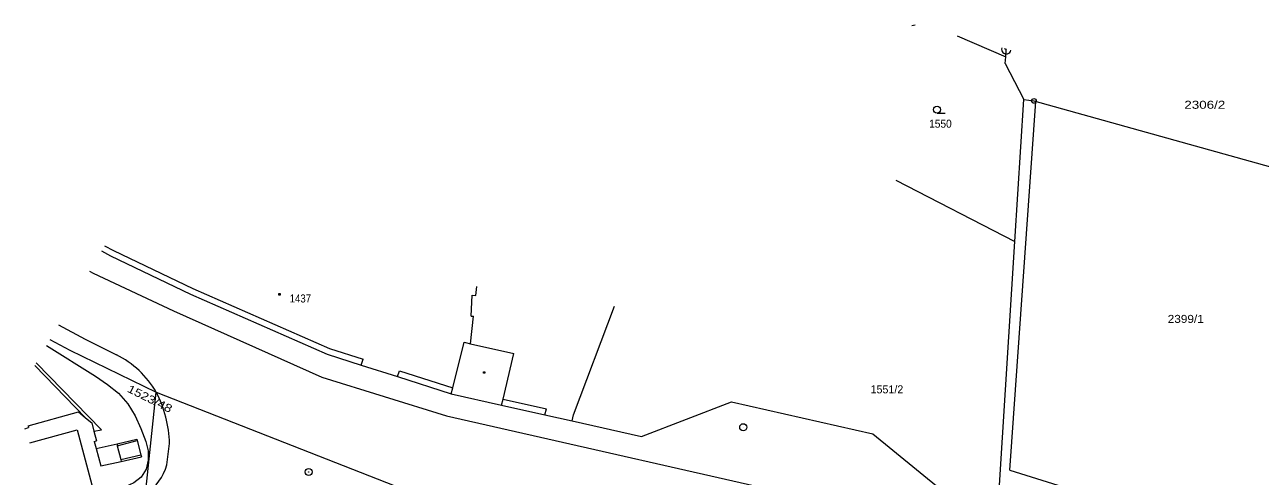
# Model space of a CAD drawing. Extents: x -630464 to -630140, y -1004543 to -1004208.
# Drawn here: x -630461.7 to -630330.5, y -1004256.3 to -1004208.4 of the extents above; entities that cross this region are included whole.
import ezdxf

# ---------------------------------------------------------------- set-up
doc = ezdxf.new("R2010")
doc.units = 0
doc.header["$LTSCALE"] = 0.34
for name, color, linetype, lineweight in [('1', 7, 'Continuous', 13), ('2', 7, 'Continuous', 13), ('23', 7, 'Continuous', 13), ('25', 7, 'Continuous', 13), ('28', 7, 'Continuous', 13)]:
    doc.layers.add(name, color=color, linetype=linetype, lineweight=lineweight)
doc.layers.add('14', color=7, linetype='Continuous')
doc.layers.add('15', color=7, linetype='Continuous')

msp = doc.modelspace()

# ---------------------------------------------------------------- linework, layer by layer
at = {"layer": '1'}
for p, q in [((-630367.482, -1004208.456), (-630367.141, -1004208.355)), ((-630357.678, -1004210.884), (-630357.45, -1004210.96)), ((-630357.45, -1004210.96), (-630357.449, -1004210.945)), ((-630357.56, -1004212.49), (-630355.58, -1004216.31)), ((-630356.54, -1004231.37), (-630355.58, -1004216.31)), ((-630369.197, -1004224.868), (-630356.54, -1004231.37)), ((-630358.18, -1004257.25), (-630356.54, -1004231.37)), ((-630453.543, -1004232.382), (-630452.58, -1004232.91)), ((-630403.43, -1004249.79), (-630399.057, -1004238.251)), ((-630459.017, -1004241.765), (-630456.91, -1004242.93)), ((-630456.91, -1004242.93), (-630447.73, -1004247.37)), ((-630448.86, -1004258.16), (-630447.73, -1004247.37)), ((-630447.73, -1004247.37), (-630421.48, -1004257.69)), ((-630403.57, -1004250.43), (-630403.43, -1004249.79)), ((-630403.57, -1004250.43), (-630396.18, -1004252.07))]:
    msp.add_line(p, q, dxfattribs=at)
for points in [[(-630357.56, -1004212.49), (-630357.51, -1004211.76), (-630357.45, -1004210.96)], [(-630355.58, -1004216.31), (-630354.52, -1004216.45), (-630337.4, -1004221.2), (-630327.89, -1004223.88), (-630326.61, -1004224.26), (-630325.46, -1004224.42), (-630324.8, -1004224.32), (-630324.07, -1004223.66), (-630323.93, -1004223.2), (-630323.87, -1004223.43), (-630317.98, -1004229.42)], [(-630452.58, -1004232.91), (-630444.1, -1004236.96), (-630429.57, -1004243.34), (-630425.95, -1004244.49), (-630422.1, -1004245.72), (-630416.39, -1004247.54), (-630411.05, -1004248.76), (-630406.45, -1004249.79), (-630403.57, -1004250.43)], [(-630459.399, -1004242.419), (-630454.17, -1004245.68), (-630452.92, -1004246.55), (-630451.74, -1004247.48), (-630450.75, -1004248.61), (-630449.97, -1004249.9), (-630449.35, -1004251.22), (-630448.83, -1004252.61), (-630448.6, -1004253.59), (-630448.58, -1004254.59), (-630448.79, -1004255.56), (-630449.34, -1004256.4), (-630450.11, -1004257.02), (-630451.03, -1004257.43), (-630452.32, -1004257.76), (-630454.28, -1004258.29)], [(-630396.18, -1004252.07), (-630386.63, -1004248.4), (-630371.62, -1004251.8), (-630361.95, -1004259.68)]]:
    msp.add_lwpolyline(points, dxfattribs=at)
at = {"layer": '2'}
for p, q in [((-630362.673, -1004209.549), (-630357.51, -1004211.76)), ((-630357.09, -1004255.65), (-630354.33, -1004216.52)), ((-630354.52, -1004216.45), (-630354.33, -1004216.52)), ((-630453.215, -1004231.82), (-630452.28, -1004232.33)), ((-630452.28, -1004232.33), (-630443.83, -1004236.37)), ((-630454.801, -1004234.538), (-630454.43, -1004234.74)), ((-630454.43, -1004234.74), (-630445.9, -1004238.74)), ((-630443.83, -1004236.37), (-630429.34, -1004242.73)), ((-630413.78, -1004237.12), (-630413.665, -1004236.14)), ((-630414.3, -1004239.3), (-630414.17, -1004237.08)), ((-630414.17, -1004237.08), (-630413.78, -1004237.12)), ((-630445.9, -1004238.74), (-630430.13, -1004245.79)), ((-630414.35, -1004242.23), (-630414.04, -1004239.32)), ((-630414.3, -1004239.3), (-630414.04, -1004239.32)), ((-630458.116, -1004240.221), (-630455.26, -1004241.73)), ((-630455.26, -1004241.73), (-630451.96, -1004243.41)), ((-630429.34, -1004242.73), (-630425.75, -1004243.87)), ((-630416.23, -1004246.9), (-630415.03, -1004242.07)), ((-630415.03, -1004242.07), (-630414.89, -1004242.1)), ((-630414.89, -1004242.1), (-630414.35, -1004242.23)), ((-630414.35, -1004242.23), (-630409.75, -1004243.28)), ((-630410.9, -1004248.13), (-630409.75, -1004243.28)), ((-630460.632, -1004244.533), (-630455.24, -1004250.09)), ((-630460.475, -1004244.264), (-630453.55, -1004251.36)), ((-630425.95, -1004244.49), (-630425.75, -1004243.87)), ((-630430.13, -1004245.79), (-630416.92, -1004249.88)), ((-630422.1, -1004245.72), (-630421.9, -1004245.1)), ((-630421.9, -1004245.1), (-630416.23, -1004246.9)), ((-630416.39, -1004247.54), (-630416.23, -1004246.9)), ((-630411.05, -1004248.76), (-630410.9, -1004248.13)), ((-630410.9, -1004248.13), (-630406.3, -1004249.15)), ((-630461.33, -1004250.95), (-630455.98, -1004249.47)), ((-630455.98, -1004249.47), (-630455.24, -1004250.09)), ((-630406.45, -1004249.79), (-630406.3, -1004249.15)), ((-630461.696, -1004251.255), (-630461.28, -1004251.14)), ((-630461.33, -1004250.95), (-630461.28, -1004251.14)), ((-630416.92, -1004249.88), (-630331.87, -1004269.15)), ((-630461.161, -1004252.77), (-630456.14, -1004251.38)), ((-630456.14, -1004251.38), (-630454.28, -1004258.29)), ((-630454.34, -1004251.52), (-630453.55, -1004251.36)), ((-630454.34, -1004251.52), (-630454.07, -1004252.53)), ((-630451.87, -1004252.87), (-630449.8, -1004252.37)), ((-630454.31, -1004252.6), (-630454.07, -1004252.53)), ((-630454.31, -1004252.6), (-630454.11, -1004253.36)), ((-630454.11, -1004253.36), (-630451.87, -1004252.87)), ((-630454.11, -1004253.36), (-630453.61, -1004255.2)), ((-630451.86, -1004253.07), (-630449.74, -1004252.52)), ((-630446.61, -1004255.09), (-630446.32, -1004252.83)), ((-630453.61, -1004255.2), (-630451.44, -1004254.72)), ((-630451.48, -1004254.53), (-630449.37, -1004254.03)), ((-630451.48, -1004254.53), (-630451.44, -1004254.72)), ((-630451.44, -1004254.72), (-630449.31, -1004254.25)), ((-630449.37, -1004254.03), (-630449.31, -1004254.25)), ((-630357.09, -1004255.65), (-630329.39, -1004264.29))]:
    msp.add_line(p, q, dxfattribs=at)
for points in [[(-630455.24, -1004250.09), (-630454.58, -1004250.64), (-630454.34, -1004251.52)], [(-630449.8, -1004252.37), (-630449.74, -1004252.52), (-630449.37, -1004254.03)], [(-630451.87, -1004252.87), (-630451.86, -1004253.07), (-630451.48, -1004254.53)]]:
    msp.add_lwpolyline(points, dxfattribs=at)
for centre, radius, start, end in [((-630456.388, -1004252.379), 10.002, 30.05096, 63.72541), ((-630458.659, -1004253.104), 12.342, 1.27399, 27.68564), ((-630451.719, -1004253.705), 5.294, 302.69259, 344.8321)]:
    msp.add_arc(centre, radius, start, end, dxfattribs=at)
at = {"layer": '23'}
msp.add_line((-630364.81, -1004217.75), (-630363.935, -1004217.75), dxfattribs=at)
msp.add_circle((-630364.81, -1004217.375), 0.375, dxfattribs=at)
at = {"layer": '25'}
for points in [[(-630434.72, -1004236.91), (-630434.57, -1004236.91), (-630434.57, -1004237.06), (-630434.72, -1004237.06)], [(-630412.97, -1004245.2), (-630412.82, -1004245.2), (-630412.82, -1004245.35), (-630412.97, -1004245.35)]]:
    msp.add_lwpolyline(points, close=True, dxfattribs=at)
at = {"layer": '28'}
for centre, radius in [((-630357.45, -1004210.96), 0.01), ((-630354.52, -1004216.45), 0.25), ((-630354.52, -1004216.45), 0.005), ((-630385.39, -1004251.1), 0.375), ((-630385.39, -1004251.1), 0.005), ((-630431.54, -1004255.85), 0.375), ((-630431.54, -1004255.85), 0.005)]:
    msp.add_circle(centre, radius, dxfattribs=at)
msp.add_arc((-630357.45, -1004210.96), 0.5, 163.36848, 346.7038, dxfattribs=at)

# ---------------------------------------------------------------- texts
at = {"layer": '14'}
for s, width, p in [('2306/2', 1.25, (-630338.545, -1004217.28)), ('1550', 0.95, (-630365.65, -1004219.29)), ('2399/1', 1.1, (-630340.308, -1004240.02))]:
    msp.add_text(s, height=0.85, dxfattribs=dict(at, width=width)).set_placement(p)
at = {"layer": '14', "width": 1.25}
msp.add_text('1523/48', height=0.85, rotation=333.424, dxfattribs=at).set_placement((-630450.887, -1004247.3))
at = {"layer": '14'}
msp.add_text('1551/2', height=0.85, dxfattribs=at).set_placement((-630371.87, -1004247.5))
at = {"layer": '15', "width": 0.9}
msp.add_text('1437', height=0.85, dxfattribs=at).set_placement((-630433.56, -1004237.85))

doc.saveas('drawing.dxf')
